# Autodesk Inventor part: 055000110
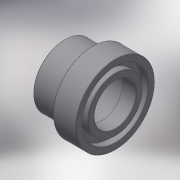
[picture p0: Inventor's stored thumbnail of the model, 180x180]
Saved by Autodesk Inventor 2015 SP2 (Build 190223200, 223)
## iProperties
Created: 2017-10
Part Number: 055000110
Material: Generic
Description: PLASSON FLANGE AD.+O-RING-CE 110
Document SubType Name: Modeling
Designer: KIM
Density: 1 g/cm^3
Appearance: Default
Author: KIM
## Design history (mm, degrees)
derived "055000.ipt"
feature "Solid1::055000.ipt"
tag "TaggingFeature1"
body "Solid1"
other parameters: "d0" = 72, "d1" = 126, "d3" = 99, "d4" = 18, "d5" = 61, "d8" = 5.4, "d11" = 1.1, "d12" = 5.4, "d15" = 7.65, "E_" = 126, "l_" = 61, "B_" = 18, "H_" = 72, "d14" = 25.5
